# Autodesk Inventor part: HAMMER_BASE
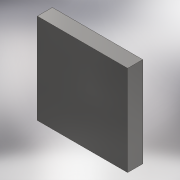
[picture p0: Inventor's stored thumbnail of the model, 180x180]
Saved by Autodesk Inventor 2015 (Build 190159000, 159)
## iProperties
Created: 2014-08
Part Number: HAMMER_BASE
Material: Steel, Mild
Document SubType Name: Modeling
Designer: lakshayg
Density: 7.85 g/cm^3
Appearance: Semi-Polished
Mass: 488.333 g
Surface Area: 138.24 cm^2
Volume: 62.208 cm^3
Author: lakshayg
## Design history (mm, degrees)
sketch "Sketch1"
  geometry: L1 (36, 36)-(-36, 36); L2 (-36, 36)-(-36, -36); L3 (-36, -36)-(36, -36); L4 (36, -36)-(36, 36); L5 (36, 36)-(-36, -36); L6 (-36, 36)-(36, -36); 1 further point
  constraints: 12 end point, 2 midpoint, 2 parallel, 1 horizontal, 1 perpendicular
  dimensions: "d0" = 72 distance of L3.end L2.end; "d1" = 72 distance of L2.end L1.end
extrude "Extrusion1" new body sketch "Sketch1" distance "d2" = 12; taper "d3" = 0 deg
body "Solid1"
